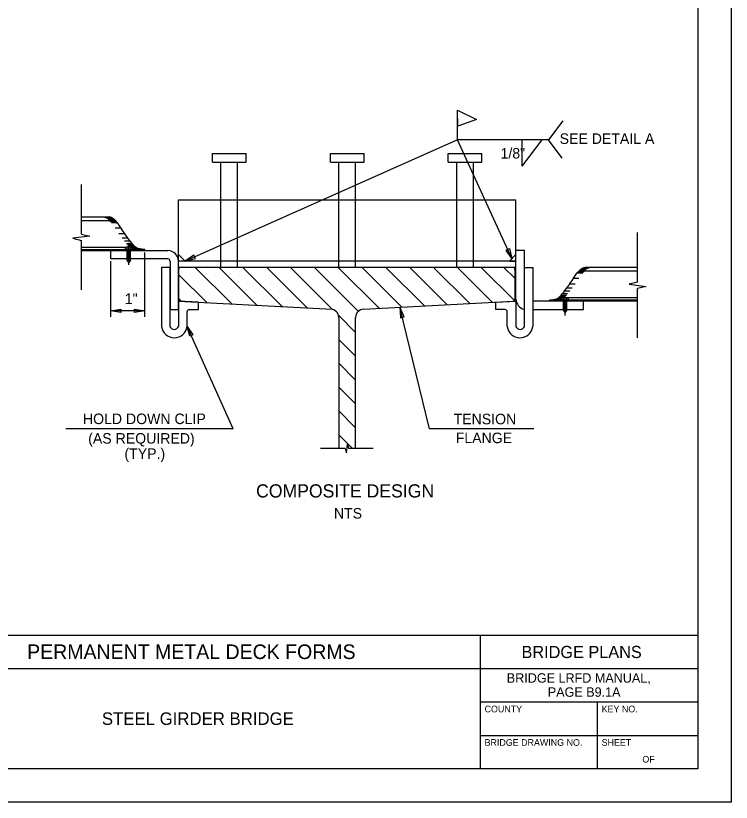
# Model space of a CAD drawing. Extents: x 0 to 34, y 0 to 23.5.
# Drawn here: x 23.3 to 34, y 0 to 11.76 of the extents above; entities that cross this region are included whole.
import ezdxf

# ---------------------------------------------------------------- set-up
doc = ezdxf.new("R2010")
doc.units = 0
for name, color, linetype in [('BORDER_ANNO_Cutsheet', 7, 'Continuous'), ('BRDG_ANNO_Anno-Sheet', 7, 'Continuous'), ('BRDG_ANNO_General-Notes', 7, 'Continuous'), ('BRDG_BASE_Dtlctrln', 7, 'Continuous'), ('BRDG_BASE_Hidden-Line', 7, 'Continuous'), ('BRDG_BASE_Obj-Line', 7, 'Continuous'), ('BRDG_BASE_Pattern', 7, 'Continuous')]:
    doc.layers.add(name, color=color, linetype=linetype)

msp = doc.modelspace()

# ---------------------------------------------------------------- linework, layer by layer
at = {"layer": 'BORDER_ANNO_Cutsheet'}
msp.add_lwpolyline([(0, 22), (34, 22), (34, 0), (0, 0)], close=True, dxfattribs=at)
at = {"layer": 'BRDG_ANNO_Anno-Sheet'}
for p, q in [((19.25, 2.5), (33.5, 2.5)), ((30.25, 0.5), (30.25, 2.5)), ((22.25, 2), (30.25, 2)), ((30.25, 2), (33.5, 2)), ((30.25, 1.5), (33.5, 1.5)), ((32, 0.5), (32, 1.5)), ((30.25, 1), (33.5, 1))]:
    msp.add_line(p, q, dxfattribs=at)
msp.add_lwpolyline([(1.5, 21.5), (33.5, 21.5), (33.5, 0.5), (1.5, 0.5)], close=True, dxfattribs=at)
at = {"layer": 'BRDG_ANNO_General-Notes'}
for p, q in [((29.909, 9.904), (29.909, 10.348)), ((31.48, 10.187), (31.268, 9.904)), ((29.909, 9.904), (25.833, 8.09)), ((31.268, 9.904), (29.909, 9.904)), ((30.721, 8.128), (29.909, 9.904)), ((30.874, 9.507), (30.874, 9.904)), ((30.874, 9.507), (31.171, 9.904)), ((31.473, 9.63), (31.268, 9.904)), ((30.635, 8.255), (30.682, 8.277)), ((30.721, 8.128), (30.635, 8.255)), ((30.682, 8.277), (30.721, 8.128)), ((25.231, 7.256), (25.231, 8.22)), ((25.965, 8.18), (25.833, 8.09)), ((25.833, 8.09), (25.988, 8.127)), ((25.988, 8.127), (25.965, 8.18)), ((24.723, 7.256), (24.723, 8.087)), ((24.723, 7.345), (24.873, 7.37)), ((25.227, 7.345), (24.723, 7.345)), ((24.873, 7.319), (24.723, 7.345)), ((24.873, 7.37), (24.873, 7.319)), ((25.079, 7.319), (25.079, 7.37)), ((25.079, 7.37), (25.231, 7.345)), ((25.231, 7.345), (25.079, 7.319)), ((29.49, 5.584), (29.046, 7.4)), ((29.046, 7.4), (29.055, 7.24)), ((29.112, 7.254), (29.046, 7.4)), ((29.055, 7.24), (29.112, 7.254)), ((26.553, 5.584), (25.864, 7.114)), ((25.904, 6.965), (25.864, 7.114)), ((25.864, 7.114), (25.95, 6.986)), ((25.95, 6.986), (25.904, 6.965)), ((26.553, 5.584), (24.05, 5.584)), ((31.046, 5.584), (29.49, 5.584))]:
    msp.add_line(p, q, dxfattribs=at)
msp.add_lwpolyline([(29.909, 10.348), (30.189, 10.206), (29.91, 10.106)], close=True, dxfattribs=at)
at = {"layer": 'BRDG_BASE_Dtlctrln'}
for p, q in [((24.995, 8.032), (24.995, 8.365)), ((31.518, 7.276), (31.518, 7.587))]:
    msp.add_line(p, q, dxfattribs=at)
at = {"layer": 'BRDG_BASE_Hidden-Line'}
for p, q in [((26.368, 9.003), (26.62, 9.003)), ((28.132, 9.003), (28.384, 9.003)), ((29.895, 9.003), (30.147, 9.003)), ((26.62, 8.09), (26.368, 8.09)), ((28.384, 8.09), (28.132, 8.09)), ((30.147, 8.09), (29.895, 8.09))]:
    msp.add_line(p, q, dxfattribs=at)
at = {"layer": 'BRDG_BASE_Obj-Line'}
for p, q in [((26.242, 9.57), (26.242, 9.696)), ((26.242, 9.696), (26.746, 9.696)), ((26.746, 9.57), (26.746, 9.696)), ((28.006, 9.57), (28.006, 9.696)), ((28.006, 9.696), (28.51, 9.696)), ((28.51, 9.57), (28.51, 9.696)), ((29.769, 9.57), (29.769, 9.696)), ((29.769, 9.696), (30.273, 9.696)), ((30.273, 9.57), (30.273, 9.696)), ((26.242, 9.57), (26.746, 9.57)), ((26.368, 7.995), (26.368, 9.57)), ((26.62, 7.995), (26.62, 9.57)), ((28.006, 9.57), (28.51, 9.57)), ((28.132, 7.995), (28.132, 9.57)), ((28.384, 7.995), (28.384, 9.57)), ((29.769, 9.57), (30.273, 9.57)), ((29.895, 7.995), (29.895, 9.57)), ((30.147, 7.995), (30.147, 9.57)), ((24.283, 8.493), (24.283, 9.233)), ((25.735, 7.995), (25.735, 9.003)), ((25.735, 9.003), (26.368, 9.003)), ((26.62, 9.003), (28.132, 9.003)), ((28.384, 9.003), (29.895, 9.003)), ((30.147, 9.003), (30.781, 9.003)), ((30.781, 7.995), (30.781, 9.003)), ((24.278, 8.752), (24.697, 8.752)), ((24.632, 8.744), (24.716, 8.744)), ((24.647, 8.738), (24.731, 8.738)), ((24.659, 8.734), (24.743, 8.734)), ((24.675, 8.727), (24.758, 8.727)), ((24.686, 8.718), (24.769, 8.718)), ((24.69, 8.71), (24.775, 8.71)), ((24.7, 8.701), (24.784, 8.701)), ((24.278, 8.695), (24.791, 8.695)), ((24.709, 8.686), (24.793, 8.686)), ((24.717, 8.68), (24.801, 8.68)), ((24.734, 8.665), (24.817, 8.665)), ((24.79, 8.586), (24.874, 8.586)), ((24.283, 8.493), (24.409, 8.462)), ((24.846, 8.503), (24.93, 8.503)), ((32.6, 7.775), (32.6, 8.515)), ((24.409, 8.462), (24.157, 8.43)), ((24.157, 8.43), (24.283, 8.399)), ((24.283, 7.659), (24.283, 8.399)), ((24.891, 8.438), (24.975, 8.438)), ((24.928, 8.395), (25.011, 8.395)), ((24.959, 8.354), (25.043, 8.354)), ((24.278, 8.296), (24.939, 8.296)), ((24.278, 8.261), (25.231, 8.261)), ((24.278, 8.247), (24.724, 8.247)), ((24.278, 8.247), (24.97, 8.247)), ((24.723, 8.121), (24.723, 8.247)), ((24.723, 8.247), (24.97, 8.247)), ((24.944, 8.263), (24.944, 8.295)), ((25.043, 8.261), (24.947, 8.261)), ((25.033, 8.299), (24.957, 8.299)), ((24.97, 8.261), (24.97, 8.295)), ((24.97, 8.106), (24.97, 8.261)), ((25.02, 8.228), (24.97, 8.249)), ((24.974, 8.331), (25.058, 8.331)), ((25.02, 8.248), (24.99, 8.26)), ((24.993, 8.313), (25.076, 8.313)), ((24.997, 8.306), (25.081, 8.306)), ((25.002, 8.301), (25.086, 8.301)), ((25.02, 8.261), (25.02, 8.295)), ((25.02, 8.106), (25.02, 8.261)), ((25.02, 8.247), (25.577, 8.247)), ((25.045, 8.263), (25.045, 8.295)), ((25.049, 8.296), (25.096, 8.296)), ((25.052, 8.289), (25.105, 8.289)), ((25.052, 8.283), (25.117, 8.283)), ((25.057, 8.275), (25.132, 8.275)), ((25.073, 8.269), (25.157, 8.269)), ((25.231, 8.248), (25.231, 8.261)), ((30.907, 8.247), (30.781, 8.247)), ((30.781, 7.523), (30.781, 8.247)), ((30.907, 7.523), (30.907, 8.247)), ((24.97, 8.121), (24.723, 8.121)), ((25.02, 8.133), (24.969, 8.154)), ((25.02, 8.207), (24.97, 8.228)), ((25.02, 8.187), (24.97, 8.209)), ((25.02, 8.171), (24.97, 8.192)), ((25.02, 8.152), (24.97, 8.174)), ((25.02, 8.112), (24.97, 8.132)), ((25.577, 8.121), (25.02, 8.121)), ((25.011, 8.094), (24.97, 8.111)), ((24.995, 8.071), (24.97, 8.106)), ((25.02, 8.106), (24.995, 8.071)), ((25.609, 7.995), (25.483, 7.995)), ((25.483, 7.995), (25.483, 7.114)), ((25.609, 8.09), (25.609, 7.366)), ((25.609, 7.984), (25.609, 7.995)), ((25.735, 7.366), (25.735, 8.09)), ((26.368, 8.09), (25.735, 8.09)), ((30.781, 7.995), (25.735, 7.995)), ((28.132, 8.09), (26.62, 8.09)), ((29.895, 8.09), (28.384, 8.09)), ((30.781, 8.09), (30.147, 8.09)), ((30.907, 7.995), (31.033, 7.995)), ((30.907, 7.114), (30.907, 7.995)), ((31.033, 7.995), (31.033, 7.114)), ((32.594, 7.996), (31.815, 7.996)), ((25.609, 7.114), (25.609, 7.984)), ((25.735, 7.964), (25.735, 7.492)), ((30.767, 7.52), (30.767, 7.964)), ((31.779, 7.909), (31.695, 7.909)), ((31.795, 7.925), (31.711, 7.925)), ((31.803, 7.931), (31.72, 7.931)), ((32.594, 7.939), (31.722, 7.939)), ((31.812, 7.945), (31.729, 7.945)), ((31.821, 7.954), (31.737, 7.954)), ((31.827, 7.962), (31.743, 7.962)), ((31.838, 7.971), (31.754, 7.971)), ((31.854, 7.978), (31.77, 7.978)), ((31.865, 7.983), (31.782, 7.983)), ((31.88, 7.989), (31.797, 7.989)), ((31.723, 7.83), (31.639, 7.83)), ((32.6, 7.775), (32.474, 7.744)), ((31.621, 7.683), (31.538, 7.683)), ((31.667, 7.747), (31.582, 7.747)), ((32.474, 7.744), (32.726, 7.712)), ((32.726, 7.712), (32.6, 7.681)), ((32.6, 6.941), (32.6, 7.681)), ((31.46, 7.527), (31.396, 7.527)), ((31.461, 7.533), (31.408, 7.533)), ((31.463, 7.54), (31.416, 7.54)), ((31.51, 7.546), (31.426, 7.546)), ((31.515, 7.551), (31.431, 7.551)), ((31.52, 7.558), (31.436, 7.558)), ((31.539, 7.575), (31.455, 7.575)), ((31.467, 7.507), (31.467, 7.539)), ((31.553, 7.598), (31.47, 7.598)), ((31.48, 7.543), (31.555, 7.543)), ((31.492, 7.505), (31.492, 7.539)), ((31.584, 7.639), (31.5, 7.639)), ((31.543, 7.505), (31.543, 7.539)), ((31.568, 7.507), (31.568, 7.539)), ((32.594, 7.54), (31.572, 7.54)), ((25.735, 7.492), (28.035, 7.371)), ((25.735, 7.366), (25.735, 7.492)), ((26.035, 7.476), (25.735, 7.492)), ((25.735, 7.492), (25.735, 7.114)), ((26.035, 7.366), (26.035, 7.476)), ((28.503, 7.372), (30.737, 7.489)), ((30.481, 7.476), (30.781, 7.492)), ((30.481, 7.366), (30.481, 7.476)), ((30.781, 7.492), (30.781, 7.114)), ((31.492, 7.492), (31.033, 7.492)), ((32.594, 7.505), (31.282, 7.505)), ((31.282, 7.493), (31.282, 7.505)), ((31.439, 7.513), (31.356, 7.513)), ((31.457, 7.519), (31.38, 7.519)), ((31.47, 7.505), (31.565, 7.505)), ((31.492, 7.35), (31.492, 7.505)), ((31.492, 7.472), (31.542, 7.494)), ((31.492, 7.451), (31.543, 7.472)), ((31.492, 7.432), (31.543, 7.453)), ((31.492, 7.415), (31.543, 7.436)), ((31.492, 7.396), (31.543, 7.418)), ((31.493, 7.493), (31.525, 7.505)), ((31.543, 7.35), (31.543, 7.505)), ((32.596, 7.492), (31.543, 7.492)), ((31.792, 7.492), (31.543, 7.492)), ((31.792, 7.366), (31.792, 7.492)), ((25.609, 7.366), (25.735, 7.366)), ((25.864, 7.114), (25.864, 7.334)), ((25.896, 7.366), (26.035, 7.366)), ((30.619, 7.366), (30.481, 7.366)), ((30.65, 7.114), (30.65, 7.334)), ((31.033, 7.366), (31.492, 7.366)), ((31.492, 7.377), (31.543, 7.398)), ((31.492, 7.356), (31.542, 7.376)), ((31.492, 7.35), (31.518, 7.315)), ((31.501, 7.338), (31.543, 7.355)), ((31.518, 7.315), (31.543, 7.35)), ((31.543, 7.366), (31.792, 7.366)), ((28.132, 7.247), (28.132, 5.291)), ((28.384, 5.291), (28.384, 7.247)), ((28.245, 5.225), (28.261, 5.351)), ((28.261, 5.351), (28.276, 5.288)), ((28.229, 5.288), (27.859, 5.288)), ((28.229, 5.288), (28.245, 5.225)), ((28.646, 5.288), (28.276, 5.288))]:
    msp.add_line(p, q, dxfattribs=at)
for points in [[(25.833, 8.09), (25.735, 8.09), (25.735, 8.188)], [(30.683, 8.09), (30.781, 8.09), (30.781, 8.188)]]:
    msp.add_lwpolyline(points, close=True, dxfattribs=at)
for centre, radius, start, end in [((24.957, 8.279), 0.0199, 50.7833, 129.2167), ((24.947, 8.263), 0.00252, 180, 270), ((24.995, 8.229), 0.0701, 68.9268, 111.0732), ((25.033, 8.279), 0.0199, 50.7833, 129.2167), ((25.043, 8.263), 0.00252, 270, 0), ((25.577, 8.09), 0.157, 0, 90), ((25.577, 8.09), 0.0315, 0, 90), ((25.766, 7.964), 0.0315, 90, 180), ((30.735, 7.964), 0.0315, 0, 90), ((31.48, 7.523), 0.0199, 50.7833, 129.2167), ((31.518, 7.473), 0.0701, 68.9268, 111.0732), ((31.555, 7.523), 0.0199, 50.7833, 129.2167), ((30.735, 7.52), 0.0315, 272.9758, 0), ((30.938, 7.523), 0.157, 180, 258.5069), ((31.47, 7.507), 0.00252, 180, 270), ((31.565, 7.507), 0.00252, 270, 360), ((25.896, 7.334), 0.0315, 90, 180), ((28.006, 7.246), 0.126, 0, 86.9884), ((28.509, 7.246), 0.126, 93.0147, 180), ((30.619, 7.334), 0.0315, 0, 90), ((25.674, 7.135), 0.192, 186.4588, 353.5412), ((25.671, 7.135), 0.0665, 198.7585, 341.2415), ((30.841, 7.135), 0.192, 186.4588, 353.5412), ((30.844, 7.135), 0.0665, 198.7585, 341.2415)]:
    msp.add_arc(centre, radius, start, end, dxfattribs=at)
for points in [[(25.231, 8.261), (25.188, 8.267), (25.157, 8.272), (25.106, 8.29), (25.058, 8.335), (24.909, 8.534), (24.848, 8.626), (24.778, 8.71), (24.744, 8.734), (24.697, 8.752)], [(31.282, 7.505), (31.324, 7.511), (31.356, 7.516), (31.407, 7.534), (31.455, 7.579), (31.604, 7.778), (31.665, 7.87), (31.735, 7.954), (31.769, 7.979), (31.815, 7.996)]]:
    msp.add_spline(points, degree=3, dxfattribs=at)
at = {"layer": 'BRDG_BASE_Pattern'}
for p, q in [((26.532, 7.449), (25.986, 7.995)), ((26.908, 7.43), (26.342, 7.995)), ((27.284, 7.41), (26.699, 7.995)), ((27.659, 7.39), (27.055, 7.995)), ((28.035, 7.371), (27.411, 7.995)), ((28.422, 7.34), (27.768, 7.995)), ((28.735, 7.384), (28.124, 7.995)), ((29.074, 7.402), (28.48, 7.995)), ((29.412, 7.42), (28.836, 7.995)), ((29.751, 7.436), (29.193, 7.995)), ((30.089, 7.454), (29.549, 7.995)), ((30.428, 7.472), (29.905, 7.995)), ((30.767, 7.49), (30.261, 7.995)), ((30.764, 7.832), (30.601, 7.995)), ((26.162, 7.464), (25.735, 7.891)), ((25.777, 7.492), (25.735, 7.535)), ((28.384, 7.023), (28.132, 7.275)), ((28.384, 6.667), (28.132, 6.919)), ((28.384, 6.311), (28.132, 6.563)), ((28.384, 5.954), (28.132, 6.206)), ((28.384, 5.598), (28.132, 5.85)), ((28.334, 5.291), (28.132, 5.494))]:
    msp.add_line(p, q, dxfattribs=at)

# ---------------------------------------------------------------- texts
at = {"layer": 'BRDG_ANNO_Anno-Sheet'}
for s, height, p in [('PERMANENT METAL DECK FORMS', 0.21813, (23.473, 2.141)), ('BRIDGE PLANS', 0.18187, (30.864, 2.156)), ('BRIDGE LRFD MANUAL,', 0.14062, (30.644, 1.788)), ('PAGE B9.1A', 0.1406, (31.257, 1.577)), ('COUNTY', 0.0994, (30.312, 1.344)), ('KEY NO.', 0.0994, (32.062, 1.344)), ('STEEL GIRDER BRIDGE', 0.1875, (24.59, 1.156)), ('BRIDGE DRAWING NO.', 0.09937, (30.312, 0.844)), ('SHEET', 0.0994, (32.062, 0.844)), ('OF', 0.0994, (32.671, 0.594))]:
    msp.add_text(s, height=height, dxfattribs=at).set_placement(p)
at = {"layer": 'BRDG_ANNO_General-Notes'}
for s, height, p in [('SEE DETAIL A', 0.15745, (31.434, 9.841)), ('1/8"', 0.1574, (30.551, 9.623)), ('1"', 0.1575, (24.932, 7.448)), ('HOLD DOWN CLIP', 0.15745, (24.307, 5.653)), ('TENSION', 0.1574, (29.849, 5.65)), ('(AS REQUIRED)', 0.15745, (24.386, 5.361)), ('FLANGE', 0.1574, (29.881, 5.368)), ('(TYP.)', 0.1575, (24.928, 5.133)), ('COMPOSITE DESIGN', 0.19681, (26.896, 4.556)), ('NTS', 0.1575, (28.059, 4.241))]:
    msp.add_text(s, height=height, dxfattribs=at).set_placement(p)

doc.saveas('drawing.dxf')
